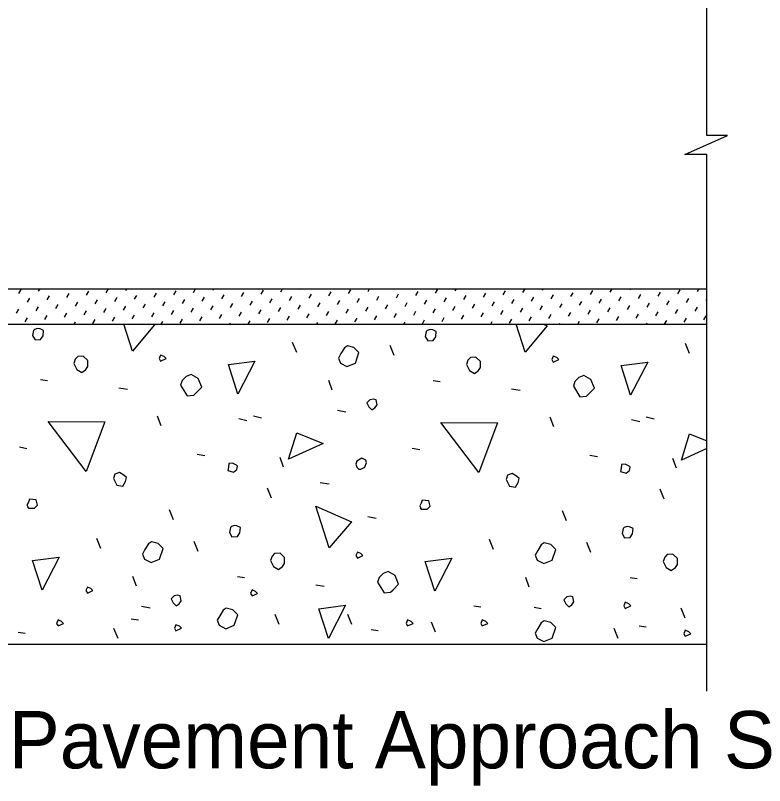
# Model space of a CAD drawing. Extents: x 130649.2 to 130733.9, y 88659.3 to 88705.5.
# Drawn here: x 130654.955 to 130657.592, y 88686.133 to 88688.843 of the extents above; entities that cross this region are included whole.
import ezdxf

# ---------------------------------------------------------------- set-up
doc = ezdxf.new("R2010")
doc.units = 0
for name, color, linetype in [('AdhocPoint_dp', 7, 'Continuous'), ('PlotBorder_dp', 7, 'Continuous'), ('TextMisc', 7, 'Continuous')]:
    doc.layers.add(name, color=color, linetype=linetype)

msp = doc.modelspace()

# ---------------------------------------------------------------- linework, layer by layer
at = {"layer": 'AdhocPoint_dp'}
for p, q in [((130649.8579, 88687.8812), (130657.3892, 88687.8812)), ((130649.8579, 88687.7562), (130657.3892, 88687.7562)), ((130649.8579, 88686.6312), (130657.3892, 88686.6312))]:
    msp.add_line(p, q, dxfattribs=at)
at = {"layer": 'PlotBorder_dp'}
for points in [[(130657.3892, 88688.7146), (130657.3892, 88689.6018), (130657.3117, 88689.6018), (130657.4617, 88689.668), (130657.3892, 88689.668), (130657.3892, 88691.4813)], [(130657.3892, 88686.4655), (130657.3892, 88688.3538), (130657.3117, 88688.3538), (130657.4617, 88688.4201), (130657.3892, 88688.4201), (130657.3892, 88688.7146)]]:
    msp.add_lwpolyline(points, dxfattribs=at)
at = {"layer": 'TextMisc'}
for p, q in [((130654.9675, 88687.8644), (130654.9756, 88687.8784)), ((130655.0366, 88687.8725), (130655.0417, 88687.8812)), ((130655.1058, 88687.8806), (130655.1061, 88687.8812)), ((130655.2055, 88687.8582), (130655.2136, 88687.8722)), ((130655.2747, 88687.8663), (130655.2828, 88687.8803)), ((130655.3438, 88687.8744), (130655.3478, 88687.8812)), ((130655.5127, 88687.8601), (130655.5208, 88687.8741)), ((130655.5818, 88687.8682), (130655.5894, 88687.8812)), ((130655.651, 88687.8763), (130655.6539, 88687.8812)), ((130655.8199, 88687.862), (130655.828, 88687.876)), ((130655.889, 88687.8701), (130655.8955, 88687.8812)), ((130655.9582, 88687.8782), (130655.9599, 88687.8812)), ((130656.1271, 88687.8639), (130656.1352, 88687.8778)), ((130656.1962, 88687.872), (130656.2016, 88687.8812)), ((130656.2654, 88687.8801), (130656.266, 88687.8812)), ((130656.3651, 88687.8576), (130656.3732, 88687.8716)), ((130656.4342, 88687.8657), (130656.4423, 88687.8797)), ((130656.5034, 88687.8738), (130656.5077, 88687.8812)), ((130656.6723, 88687.8595), (130656.6804, 88687.8735)), ((130656.7414, 88687.8676), (130656.7493, 88687.8812)), ((130656.8106, 88687.8757), (130656.8138, 88687.8812)), ((130656.9794, 88687.8614), (130656.9875, 88687.8754)), ((130657.0486, 88687.8695), (130657.0554, 88687.8812)), ((130657.1178, 88687.8776), (130657.1199, 88687.8812)), ((130657.2866, 88687.8633), (130657.2947, 88687.8773)), ((130657.3558, 88687.8714), (130657.3615, 88687.8812)), ((130654.998, 88687.8339), (130655.0061, 88687.8479)), ((130655.0672, 88687.842), (130655.0753, 88687.856)), ((130655.1363, 88687.8501), (130655.1444, 88687.8641)), ((130655.3052, 88687.8358), (130655.3133, 88687.8498)), ((130655.3744, 88687.8439), (130655.3825, 88687.8579)), ((130655.4435, 88687.852), (130655.4516, 88687.866)), ((130655.5432, 88687.8296), (130655.5513, 88687.8436)), ((130655.6124, 88687.8377), (130655.6205, 88687.8517)), ((130655.6815, 88687.8458), (130655.6896, 88687.8598)), ((130655.7507, 88687.8539), (130655.7588, 88687.8679)), ((130655.8504, 88687.8314), (130655.8585, 88687.8454)), ((130655.9196, 88687.8395), (130655.9277, 88687.8535)), ((130655.9887, 88687.8476), (130655.9968, 88687.8616)), ((130656.0579, 88687.8558), (130656.066, 88687.8697)), ((130656.1576, 88687.8333), (130656.1657, 88687.8473)), ((130656.2267, 88687.8414), (130656.2348, 88687.8554)), ((130656.2959, 88687.8495), (130656.304, 88687.8635)), ((130656.4648, 88687.8352), (130656.4729, 88687.8492)), ((130656.5339, 88687.8433), (130656.542, 88687.8573)), ((130656.6031, 88687.8514), (130656.6112, 88687.8654)), ((130656.772, 88687.8371), (130656.7801, 88687.8511)), ((130656.8411, 88687.8452), (130656.8492, 88687.8592)), ((130656.9103, 88687.8533), (130656.9184, 88687.8673)), ((130657.01, 88687.8309), (130657.0181, 88687.8449)), ((130657.0791, 88687.839), (130657.0872, 88687.853)), ((130657.1483, 88687.8471), (130657.1564, 88687.8611)), ((130657.2175, 88687.8552), (130657.2256, 88687.8692)), ((130657.3172, 88687.8327), (130657.3253, 88687.8467)), ((130657.3863, 88687.8408), (130657.3892, 88687.8459)), ((130655.0285, 88687.8034), (130655.0366, 88687.8174)), ((130655.0977, 88687.8115), (130655.1058, 88687.8255)), ((130655.1669, 88687.8196), (130655.175, 88687.8336)), ((130655.236, 88687.8277), (130655.2441, 88687.8417)), ((130655.3357, 88687.8053), (130655.3438, 88687.8193)), ((130655.4049, 88687.8134), (130655.413, 88687.8274)), ((130655.474, 88687.8215), (130655.4821, 88687.8355)), ((130655.6429, 88687.8071), (130655.651, 88687.8211)), ((130655.7121, 88687.8152), (130655.7202, 88687.8292)), ((130655.7812, 88687.8233), (130655.7893, 88687.8373)), ((130655.9501, 88687.809), (130655.9582, 88687.823)), ((130656.0193, 88687.8171), (130656.0274, 88687.8311)), ((130656.0884, 88687.8252), (130656.0965, 88687.8392)), ((130656.1881, 88687.8028), (130656.1962, 88687.8168)), ((130656.2573, 88687.8109), (130656.2654, 88687.8249)), ((130656.3264, 88687.819), (130656.3345, 88687.833)), ((130656.3956, 88687.8271), (130656.4037, 88687.8411)), ((130656.4953, 88687.8047), (130656.5034, 88687.8187)), ((130656.5645, 88687.8128), (130656.5726, 88687.8268)), ((130656.6336, 88687.8209), (130656.6417, 88687.8349)), ((130656.7028, 88687.829), (130656.7109, 88687.843)), ((130656.8025, 88687.8065), (130656.8106, 88687.8205)), ((130656.8717, 88687.8147), (130656.8798, 88687.8286)), ((130656.9408, 88687.8228), (130656.9489, 88687.8367)), ((130657.1097, 88687.8084), (130657.1178, 88687.8224)), ((130657.1788, 88687.8165), (130657.1869, 88687.8305)), ((130657.248, 88687.8246), (130657.2561, 88687.8386)), ((130657.3477, 88687.8022), (130657.3558, 88687.8162)), ((130654.9594, 88687.7953), (130654.9675, 88687.8093)), ((130655.1282, 88687.781), (130655.1363, 88687.7949)), ((130655.1974, 88687.7891), (130655.2055, 88687.8031)), ((130655.2666, 88687.7972), (130655.2747, 88687.8112)), ((130655.4354, 88687.7828), (130655.4435, 88687.7968)), ((130655.5046, 88687.7909), (130655.5127, 88687.8049)), ((130655.5737, 88687.799), (130655.5818, 88687.813)), ((130655.6734, 88687.7766), (130655.6815, 88687.7906)), ((130655.7426, 88687.7847), (130655.7507, 88687.7987)), ((130655.8118, 88687.7928), (130655.8199, 88687.8068)), ((130655.8809, 88687.8009), (130655.889, 88687.8149)), ((130655.9806, 88687.7785), (130655.9887, 88687.7925)), ((130656.0498, 88687.7866), (130656.0579, 88687.8006)), ((130656.1189, 88687.7947), (130656.1271, 88687.8087)), ((130656.2878, 88687.7804), (130656.2959, 88687.7944)), ((130656.357, 88687.7885), (130656.3651, 88687.8025)), ((130656.4261, 88687.7966), (130656.4342, 88687.8106)), ((130656.595, 88687.7822), (130656.6031, 88687.7962)), ((130656.6642, 88687.7903), (130656.6723, 88687.8043)), ((130656.7333, 88687.7984), (130656.7414, 88687.8124)), ((130656.833, 88687.776), (130656.8411, 88687.79)), ((130656.9022, 88687.7841), (130656.9103, 88687.7981)), ((130656.9713, 88687.7922), (130656.9794, 88687.8062)), ((130657.0405, 88687.8003), (130657.0486, 88687.8143)), ((130657.1402, 88687.7779), (130657.1483, 88687.7919)), ((130657.2094, 88687.786), (130657.2175, 88687.8)), ((130657.2785, 88687.7941), (130657.2866, 88687.8081)), ((130654.9899, 88687.7647), (130654.998, 88687.7787)), ((130655.0591, 88687.7729), (130655.0672, 88687.7868)), ((130655.1621, 88687.7562), (130655.1669, 88687.7644)), ((130655.2279, 88687.7585), (130655.236, 88687.7725)), ((130655.2971, 88687.7666), (130655.3052, 88687.7806)), ((130655.3662, 88687.7747), (130655.3744, 88687.7887)), ((130655.4682, 88687.7562), (130655.474, 88687.7663)), ((130655.5351, 88687.7604), (130655.5432, 88687.7744)), ((130655.6043, 88687.7685), (130655.6124, 88687.7825)), ((130655.7743, 88687.7562), (130655.7812, 88687.7682)), ((130655.8423, 88687.7623), (130655.8504, 88687.7763)), ((130655.9115, 88687.7704), (130655.9196, 88687.7844)), ((130656.0159, 88687.7562), (130656.0193, 88687.7619)), ((130656.0804, 88687.7562), (130656.0884, 88687.7701)), ((130656.1495, 88687.7642), (130656.1576, 88687.7782)), ((130656.2186, 88687.7723), (130656.2267, 88687.7863)), ((130656.322, 88687.7562), (130656.3264, 88687.7638)), ((130656.3875, 88687.7579), (130656.3956, 88687.7719)), ((130656.4567, 88687.766), (130656.4648, 88687.78)), ((130656.5258, 88687.7741), (130656.5339, 88687.7881)), ((130656.6281, 88687.7562), (130656.6336, 88687.7657)), ((130656.6947, 88687.7598), (130656.7028, 88687.7738)), ((130656.7639, 88687.7679), (130656.772, 88687.7819)), ((130656.9342, 88687.7562), (130656.9408, 88687.7676)), ((130657.0019, 88687.7617), (130657.01, 88687.7757)), ((130657.071, 88687.7698), (130657.0791, 88687.7838)), ((130657.2403, 88687.7562), (130657.248, 88687.7695)), ((130657.3091, 88687.7636), (130657.3172, 88687.7776)), ((130657.3782, 88687.7717), (130657.3863, 88687.7857)), ((130655.0976, 88687.7562), (130655.0977, 88687.7563)), ((130655.4037, 88687.7562), (130655.4049, 88687.7582)), ((130655.7098, 88687.7562), (130655.7121, 88687.7601)), ((130656.5637, 88687.7562), (130656.5645, 88687.7576)), ((130656.8698, 88687.7562), (130656.8717, 88687.7595)), ((130657.1759, 88687.7562), (130657.1788, 88687.7614)), ((130655.9451, 88687.6568), (130655.9309, 88687.6922)), ((130656.288, 88687.6462), (130656.2739, 88687.6816)), ((130657.3275, 88687.6533), (130657.3133, 88687.6886)), ((130655.0435, 88687.5614), (130655.0683, 88687.5578)), ((130656.0706, 88687.5242), (130656.0582, 88687.5578)), ((130656.4259, 88687.5578), (130656.4507, 88687.5543)), ((130655.3193, 88687.5331), (130655.3493, 88687.5278)), ((130656.7017, 88687.5295), (130656.7317, 88687.5242)), ((130656.0883, 88687.4535), (130656.1183, 88687.4482)), ((130655.4678, 88687.3987), (130655.4554, 88687.4323)), ((130655.7418, 88687.4252), (130655.7701, 88687.4182)), ((130655.793, 88687.4341), (130655.8213, 88687.427)), ((130656.8502, 88687.3952), (130656.8378, 88687.4288)), ((130657.1242, 88687.4217), (130657.1525, 88687.4146)), ((130657.1754, 88687.4305), (130657.2037, 88687.4235)), ((130654.9693, 88687.3245), (130654.9958, 88687.3192)), ((130656.3517, 88687.3209), (130656.3782, 88687.3156)), ((130655.5951, 88687.2997), (130655.6216, 88687.2944)), ((130655.8991, 88687.2538), (130655.8867, 88687.2874)), ((130656.9775, 88687.2962), (130657.004, 88687.2909)), ((130657.2815, 88687.2502), (130657.2691, 88687.2838)), ((130656.0282, 88687.199), (130656.06, 88687.1954)), ((130655.8567, 88687.1442), (130655.8425, 88687.1795)), ((130657.2391, 88687.1406), (130657.2249, 88687.176)), ((130655.512, 88687.0681), (130655.4978, 88687.1035)), ((130656.8944, 88687.0646), (130656.8802, 88687.1)), ((130656.1961, 88687.0805), (130656.2244, 88687.0735)), ((130655.2556, 88686.9674), (130655.2415, 88687.0027)), ((130655.5986, 88686.9568), (130655.5845, 88686.9921)), ((130656.638, 88686.9638), (130656.6239, 88686.9992)), ((130656.981, 88686.9532), (130656.9668, 88686.9886)), ((130655.3812, 88686.8348), (130655.3688, 88686.8684)), ((130655.7365, 88686.8684), (130655.7612, 88686.8649)), ((130656.7636, 88686.8313), (130656.7512, 88686.8649)), ((130657.1189, 88686.8649), (130657.1436, 88686.8613)), ((130656.0123, 88686.8401), (130656.0423, 88686.8348)), ((130655.3988, 88686.7641), (130655.4289, 88686.7588)), ((130656.5687, 88686.7661), (130656.5934, 88686.7626)), ((130656.7812, 88686.7606), (130656.8058, 88686.7562)), ((130655.8834, 88686.6998), (130655.8692, 88686.7351)), ((130656.1387, 88686.6998), (130656.1246, 88686.7351)), ((130657.3124, 88686.7219), (130657.2983, 88686.7572)), ((130655.363, 88686.7195), (130655.3878, 88686.7159)), ((130656.4334, 88686.6728), (130656.4192, 88686.7081)), ((130655.3162, 88686.6507), (130655.302, 88686.686)), ((130656.2077, 88686.6826), (130656.2325, 88686.6791)), ((130657.0767, 88686.6507), (130657.0626, 88686.686)), ((130657.1506, 88686.6949), (130657.1753, 88686.6914)), ((130654.9653, 88686.6728), (130654.99, 88686.6693))]:
    msp.add_line(p, q, dxfattribs=at)
for points in [[(130655.0152, 88687.7169), (130655.0241, 88687.701), (130655.0435, 88687.7028), (130655.0524, 88687.7151), (130655.0541, 88687.7346), (130655.0417, 88687.7399), (130655.0329, 88687.7417), (130655.0223, 88687.7381), (130655.0188, 88687.7346), (130655.0152, 88687.7169)], [(130655.367, 88687.6621), (130655.3364, 88687.7562)], [(130655.4398, 88687.7562), (130655.4448, 88687.754), (130655.367, 88687.6621)], [(130656.3976, 88687.7134), (130656.4065, 88687.6975), (130656.4259, 88687.6992), (130656.4347, 88687.7116), (130656.4365, 88687.7311), (130656.4241, 88687.7364), (130656.4153, 88687.7381), (130656.4047, 88687.7346), (130656.4012, 88687.7311), (130656.3976, 88687.7134)], [(130656.7494, 88687.6586), (130656.7177, 88687.7562)], [(130656.8141, 88687.7562), (130656.8272, 88687.7505), (130656.7494, 88687.6586)], [(130656.0989, 88687.6197), (130656.1219, 88687.6073), (130656.1519, 88687.6197), (130656.1643, 88687.6568), (130656.1466, 88687.6745), (130656.1236, 88687.6798), (130656.113, 88687.6727), (130656.1006, 88687.6533), (130656.0918, 88687.6374), (130656.0989, 88687.6197)], [(130655.1602, 88687.6179), (130655.1708, 88687.5967), (130655.1885, 88687.5861), (130655.2026, 88687.5967), (130655.2097, 88687.6073), (130655.2097, 88687.6285), (130655.1938, 88687.6444), (130655.1743, 88687.6427), (130655.1655, 88687.6338), (130655.1602, 88687.6179)], [(130655.466, 88687.6268), (130655.4855, 88687.6356), (130655.4784, 88687.6427), (130655.466, 88687.648), (130655.4607, 88687.6356), (130655.466, 88687.6268)], [(130655.7382, 88687.5101), (130655.7047, 88687.6144), (130655.7984, 88687.6268), (130655.7382, 88687.5101)], [(130656.5426, 88687.6144), (130656.5532, 88687.5932), (130656.5709, 88687.5826), (130656.585, 88687.5932), (130656.5921, 88687.6038), (130656.5921, 88687.625), (130656.5762, 88687.6409), (130656.5567, 88687.6391), (130656.5479, 88687.6303), (130656.5426, 88687.6144)], [(130656.8484, 88687.6232), (130656.8679, 88687.6321), (130656.8608, 88687.6391), (130656.8484, 88687.6444), (130656.8431, 88687.6321), (130656.8484, 88687.6232)], [(130657.1206, 88687.5066), (130657.0871, 88687.6109), (130657.1807, 88687.6232), (130657.1206, 88687.5066)], [(130655.5367, 88687.5419), (130655.5597, 88687.5048), (130655.5827, 88687.5066), (130655.5915, 88687.5154), (130655.611, 88687.5348), (130655.5986, 88687.5649), (130655.5738, 88687.579), (130655.5562, 88687.572), (130655.542, 88687.5578), (130655.5367, 88687.5419)], [(130656.9191, 88687.5384), (130656.9421, 88687.5012), (130656.9651, 88687.503), (130656.9739, 88687.5119), (130656.9934, 88687.5313), (130656.981, 88687.5614), (130656.9562, 88687.5755), (130656.9386, 88687.5684), (130656.9244, 88687.5543), (130656.9191, 88687.5384)], [(130656.1996, 88687.4659), (130656.2102, 88687.4553), (130656.2208, 88687.4624), (130656.2279, 88687.473), (130656.2244, 88687.4906), (130656.2155, 88687.4924), (130656.2032, 88687.4906), (130656.1926, 88687.48), (130656.1996, 88687.4659)], [(130655.2044, 88687.2379), (130655.07, 88687.4146), (130655.2698, 88687.4129), (130655.2044, 88687.2379)], [(130656.5868, 88687.2343), (130656.4524, 88687.4111), (130656.6522, 88687.4093), (130656.5868, 88687.2343)], [(130655.9168, 88687.282), (130655.9451, 88687.374), (130656.0388, 88687.3368), (130655.9168, 88687.282)], [(130657.2992, 88687.2785), (130657.3275, 88687.3704), (130657.3892, 88687.346)], [(130657.3892, 88687.319), (130657.2992, 88687.2785)], [(130656.1643, 88687.2467), (130656.1714, 88687.2467), (130656.1855, 88687.2538), (130656.1908, 88687.2697), (130656.189, 88687.2785), (130656.1749, 88687.2856), (130656.1572, 88687.275), (130656.1537, 88687.2644), (130656.1572, 88687.2538), (130656.1643, 88687.2467)], [(130655.7029, 88687.2414), (130655.7223, 88687.2361), (130655.7347, 88687.2449), (130655.7365, 88687.2573), (130655.7329, 88687.2608), (130655.7188, 88687.2679), (130655.7064, 88687.2661), (130655.7047, 88687.2538), (130655.7029, 88687.2414)], [(130657.0853, 88687.2379), (130657.1047, 88687.2325), (130657.1171, 88687.2414), (130657.1189, 88687.2538), (130657.1153, 88687.2573), (130657.1012, 88687.2644), (130657.0888, 88687.2626), (130657.0871, 88687.2502), (130657.0853, 88687.2379)], [(130655.3034, 88687.206), (130655.3122, 88687.1901), (130655.3334, 88687.1866), (130655.3423, 88687.2025), (130655.3458, 88687.2166), (130655.337, 88687.2255), (130655.3211, 88687.2343), (130655.3051, 88687.229), (130655.2998, 88687.2131), (130655.3034, 88687.206)], [(130656.6858, 88687.2025), (130656.6946, 88687.1866), (130656.7158, 88687.1831), (130656.7247, 88687.199), (130656.7282, 88687.2131), (130656.7194, 88687.2219), (130656.7034, 88687.2308), (130656.6875, 88687.2255), (130656.6822, 88687.2096), (130656.6858, 88687.2025)], [(130655.0011, 88687.1088), (130655.0223, 88687.1088), (130655.0329, 88687.1194), (130655.0276, 88687.1389), (130655.0046, 88687.1406), (130655.0011, 88687.13), (130654.9958, 88687.1212), (130655.0011, 88687.1088), (130654.9976, 88687.1123)], [(130656.06, 88686.9692), (130656.0123, 88687.1159), (130656.1378, 88687.0611), (130656.06, 88686.9692)], [(130656.3835, 88687.1053), (130656.4047, 88687.1053), (130656.4153, 88687.1159), (130656.41, 88687.1353), (130656.387, 88687.1371), (130656.3835, 88687.1265), (130656.3782, 88687.1176), (130656.3835, 88687.1053), (130656.3799, 88687.1088)], [(130655.7082, 88687.024), (130655.717, 88687.008), (130655.7365, 88687.0098), (130655.7453, 88687.0222), (130655.7471, 88687.0416), (130655.7347, 88687.0469), (130655.7259, 88687.0487), (130655.7153, 88687.0452), (130655.7117, 88687.0416), (130655.7082, 88687.024)], [(130657.0906, 88687.0204), (130657.0994, 88687.0045), (130657.1189, 88687.0063), (130657.1277, 88687.0186), (130657.1295, 88687.0381), (130657.1171, 88687.0434), (130657.1083, 88687.0452), (130657.0977, 88687.0416), (130657.0941, 88687.0381), (130657.0906, 88687.0204)], [(130655.4094, 88686.9303), (130655.4324, 88686.9179), (130655.4625, 88686.9303), (130655.4749, 88686.9674), (130655.4572, 88686.9851), (130655.4342, 88686.9904), (130655.4236, 88686.9833), (130655.4112, 88686.9638), (130655.4024, 88686.9479), (130655.4094, 88686.9303)], [(130656.7918, 88686.9267), (130656.8148, 88686.9144), (130656.8449, 88686.9267), (130656.8572, 88686.9638), (130656.8396, 88686.9815), (130656.8166, 88686.9868), (130656.806, 88686.9798), (130656.7936, 88686.9603), (130656.7848, 88686.9444), (130656.7918, 88686.9267)], [(130655.8532, 88686.925), (130655.8638, 88686.9037), (130655.8814, 88686.8931), (130655.8956, 88686.9037), (130655.9027, 88686.9144), (130655.9027, 88686.9356), (130655.8867, 88686.9515), (130655.8673, 88686.9497), (130655.8585, 88686.9409), (130655.8532, 88686.925)], [(130656.159, 88686.9338), (130656.1784, 88686.9426), (130656.1714, 88686.9497), (130656.159, 88686.955), (130656.1537, 88686.9426), (130656.159, 88686.9338)], [(130655.0488, 88686.8207), (130655.0152, 88686.925), (130655.1089, 88686.9373), (130655.0488, 88686.8207)], [(130656.4312, 88686.8171), (130656.3976, 88686.9214), (130656.4913, 88686.9338), (130656.4312, 88686.8171)], [(130657.2355, 88686.9214), (130657.2462, 88686.9002), (130657.2638, 88686.8896), (130657.278, 88686.9002), (130657.285, 88686.9108), (130657.285, 88686.932), (130657.2691, 88686.9479), (130657.2497, 88686.9462), (130657.2409, 88686.9373), (130657.2355, 88686.9214)], [(130656.2297, 88686.8489), (130656.2527, 88686.8118), (130656.2756, 88686.8136), (130656.2845, 88686.8224), (130656.3039, 88686.8419), (130656.2916, 88686.8719), (130656.2668, 88686.8861), (130656.2491, 88686.879), (130656.235, 88686.8649), (130656.2297, 88686.8489)], [(130655.2085, 88686.8105), (130655.2279, 88686.8194), (130655.2208, 88686.8264), (130655.2085, 88686.8318), (130655.2032, 88686.8194), (130655.2085, 88686.8105)], [(130655.7879, 88686.8007), (130655.8074, 88686.8096), (130655.8003, 88686.8166), (130655.7879, 88686.8219), (130655.7826, 88686.8096), (130655.7879, 88686.8007)], [(130655.5102, 88686.7765), (130655.5208, 88686.7659), (130655.5314, 88686.7729), (130655.5385, 88686.7835), (130655.535, 88686.8012), (130655.5261, 88686.803), (130655.5137, 88686.8012), (130655.5031, 88686.7906), (130655.5102, 88686.7765)], [(130656.8926, 88686.7729), (130656.9032, 88686.7623), (130656.9138, 88686.7694), (130656.9209, 88686.78), (130656.9173, 88686.7977), (130656.9085, 88686.7994), (130656.8961, 88686.7977), (130656.8855, 88686.7871), (130656.8926, 88686.7729)], [(130656.0568, 88686.6513), (130656.0233, 88686.7556), (130656.1169, 88686.768), (130656.0568, 88686.6513)], [(130657.1016, 88686.7568), (130657.1211, 88686.7657), (130657.114, 88686.7728), (130657.1016, 88686.7781), (130657.0963, 88686.7657), (130657.1016, 88686.7568)], [(130655.6723, 88686.6972), (130655.6953, 88686.6848), (130655.7254, 88686.6972), (130655.7377, 88686.7343), (130655.7201, 88686.752), (130655.6971, 88686.7573), (130655.6865, 88686.7502), (130655.6741, 88686.7307), (130655.6653, 88686.7148), (130655.6723, 88686.6972)], [(130655.1053, 88686.6951), (130655.1248, 88686.704), (130655.1177, 88686.711), (130655.1053, 88686.7163), (130655.1, 88686.704), (130655.1053, 88686.6951)], [(130656.3355, 88686.6951), (130656.3549, 88686.704), (130656.3479, 88686.711), (130656.3355, 88686.7163), (130656.3302, 88686.704), (130656.3355, 88686.6951)], [(130656.5983, 88686.6951), (130656.6177, 88686.704), (130656.6107, 88686.711), (130656.5983, 88686.7163), (130656.593, 88686.704), (130656.5983, 88686.6951)], [(130656.7918, 88686.6524), (130656.8148, 88686.6401), (130656.8449, 88686.6524), (130656.8572, 88686.6896), (130656.8396, 88686.7072), (130656.8166, 88686.7125), (130656.806, 88686.7055), (130656.7936, 88686.686), (130656.7848, 88686.6701), (130656.7918, 88686.6524)], [(130655.5203, 88686.6779), (130655.5397, 88686.6868), (130655.5327, 88686.6939), (130655.5203, 88686.6992), (130655.515, 88686.6868), (130655.5203, 88686.6779)], [(130657.3128, 88686.6586), (130657.3323, 88686.6675), (130657.3252, 88686.6745), (130657.3128, 88686.6798), (130657.3075, 88686.6675), (130657.3128, 88686.6586)]]:
    msp.add_lwpolyline(points, dxfattribs=at)

# ---------------------------------------------------------------- texts
at = {"layer": 'PlotBorder_dp'}
msp.add_text('Approach Slab (Flexible Pavement Approach Slab ', height=0.2016, dxfattribs=at).set_placement((130651.9943, 88686.1941))

doc.saveas('drawing.dxf')
